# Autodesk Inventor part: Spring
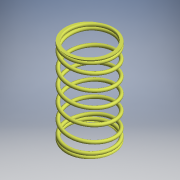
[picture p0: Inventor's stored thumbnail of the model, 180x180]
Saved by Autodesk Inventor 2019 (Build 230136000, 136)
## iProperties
Shininess: 24.0
Compacted: True
Length Units: 11272
Angle Units: 11279
Time Units: 11290
Mass Units: 11286
Length Display Precision: 4
Angle Display Precision: 2
Company: Autodesk
Created: 2000-03
Part Number: Spring
Project: Inventor Samples
User Status: IN PROGRESS
Document SubType Name: Modeling
Designer: Autodesk, Inc.
Density: 8.03 g/cm^3
Material: Stainless Steel, Austenitic
Mass: 2.926 g
Surface Area: 14.1446 cm^2
Volume: 0.364384 cm^3
Appearance: Black
Density: 0.0
Volumn: 0.0
Area: 0.0
PropertySet Name: Model Information
Control State: 0
Master: False
Checked Out: False
Checked Out Date: 2018-05-30
Last Check In Date: 2018-05-30
Author: Autodesk, Inc.
Revision Number: A
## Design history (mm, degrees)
sketch "Sketch2"
  geometry: L1 (-14.979, -10.854)-(-14.979, 14.546); A1 r 0.546 centre (-22.51, -11.4) between (-21.964, -11.4) and (-22.51, -10.854); 1 further point
  constraints: 2 end point, 2 horizontal alignment, 2 point on circle, 2 vertical alignment, 1 centre point, 1 vertical, 5 other
  dimensions: "d0" = 25.4 distance of L1.start L1.end; "d1" = 13.97 diameter of A1.start L1; "d2" = 1.0922 diameter of A1
node "Coil1" dims "d3" = 3.175 (= 0.125 x d0), "d4" = 25.4, "d5" = 50, "d6" = 0, "d7" = 30 deg, "d8" = 1 deg, "d9" = 30 deg, "d10" = 1 deg
workaxis "Work Axis1"
node "Coil2" dims "d11" = 1.1176 (computed from d2), "d12" = 25.4, "d13" = 20, "d14" = 0, "d15" = 90 deg, "d16" = 90 deg, "d17" = 0, "d18" = 0
  sketch "Sketch3"
    geometry: L1 (7.531, -5.981)-(7.531, 31.384) reference; C1 r 0.546 at (0, 0) reference
node "Extrusion1" dims "d19" = 25.4, "d20" = 0
  sketch "Sketch4"
    geometry: L1 (-2.213, -5.605)-(17.486, -5.605); L2 (17.486, -5.605)-(17.486, 0.546); L3 (17.486, 0.546)-(-2.213, 0.546); L4 (-2.213, 0.546)-(-2.213, -5.605); C1 r 0.546 at (0, 0) reference
    constraints: 8 end point, 2 parallel, 1 horizontal, 1 perpendicular, 1 tangent
node "Coil3" dims "d21" = 1.1176 (computed from d2), "d22" = 25.4, "d23" = 20, "d24" = 0, "d25" = 90 deg, "d26" = 90 deg, "d27" = 0, "d28" = 0
  sketch "Sketch5"
    geometry: L1 (-7.531, -31.381)-(-7.531, 5.984) reference; C1 r 0.546 at (0, 0) reference
node "Extrusion2" dims "d29" = 25.4, "d30" = 0
  sketch "Sketch6"
    geometry: L1 (7.067, 10.583)-(-19.265, 10.583); L2 (-19.265, 10.583)-(-19.265, -0.546); L3 (-19.265, -0.546)-(7.067, -0.546); L4 (7.067, -0.546)-(7.067, 10.583); C1 r 0.546 at (0, 0) reference
    constraints: 8 end point, 2 parallel, 1 horizontal, 1 perpendicular, 1 tangent
body "Solid1"
